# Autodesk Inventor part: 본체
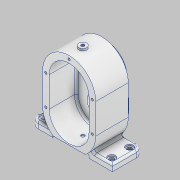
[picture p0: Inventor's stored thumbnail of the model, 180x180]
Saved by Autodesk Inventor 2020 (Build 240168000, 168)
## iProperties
Created: 2021-05
Part Number: 본체
Material: 알루미늄 6061
Document SubType Name: Modeling
Designer: Owner
Density: 2.7 g/cm^3
Appearance: 알루미늄 - 평지
Mass: 669.731 g
Surface Area: 580.57 cm^2
Volume: 248.049 cm^3
Author: Owner
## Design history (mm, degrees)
sketch "스케치3"
  geometry: L1 (0, 0)-(0, 45); L2 (40, 0)-(40, 45); L3 (-40, 45)-(-40, 0); L4 (0, -65)-(0, 110) reference; A1 r 40 centre (0, 0) between (-40, 0) and (40, 0); A2 r 40 centre (0, 45) between (40, 45) and (-40, 45); 1 further point
  constraints: 8 end point, 4 point on circle, 4 tangent, 2 centre point, 2 midpoint, 1 parallel, 1 vertical
  dimensions: "d10" = 40 radius of A2; "d11" = 45 distance of L2.start L2.end
extrude "돌출1" new body sketch "스케치3" distance "d12" = 49; taper "d13" = 0 deg
sketch "스케치4"
  geometry: L1 (0, 45)-(0, 0); L2 (-30, 45)-(-30, 0); L3 (30, 0)-(30, 45); A1 r 30 centre (0, 45) between (30, 45) and (-30, 45); A2 r 30 centre (0, 0) between (-30, 0) and (30, 0); 2 further points
  constraints: 8 end point, 4 point on circle, 4 tangent, 2 centre point, 1 coincident, 1 midpoint, 1 parallel, 1 vertical
  dimensions: "d14" = 45 distance of L3.start L3.end; "d15" = 30 radius of A1
extrude "돌출2" cut sketch "스케치4" distance "d16" = 41; taper "d17" = 0 deg
sketch "스케치5"
  geometry: L1 (0, -65)-(0, 110) reference; C1 r 14 at (0, 45); C2 r 14 at (0, 0); 2 further points
  constraints: 2 centre point, 2 coincident, 1 point on line
  dimensions: "d18" = 45 distance of point (0, 45) point (0, 0); "d19" = 28 diameter of C1; "d20" = 28 diameter of C2
extrude "돌출3" cut sketch "스케치5" distance "d21" = 8; taper "d22" = 0 deg
sketch "스케치6"
  geometry: L1 (0, 45)-(0, 0); L2 (-30, 45)-(-30, 0); L3 (30, 0)-(30, 45); A1 r 30 centre (0, 45) between (30, 45) and (-30, 45); A2 r 30 centre (0, 0) between (-30, 0) and (30, 0); 2 further points
  constraints: 8 end point, 4 point on circle, 4 tangent, 2 centre point, 1 coincident, 1 midpoint, 1 parallel, 1 vertical
  dimensions: "d23" = 30 radius of A1; "d24" = 45 distance of L2.start L2.end
extrude "돌출4" join sketch "스케치6" distance "d25" = 11; taper "d26" = 0 deg
sketch "스케치7"
  geometry: C1 r 14 at (0, 0) reference; C2 r 10 at (0, 0); 1 further point
  constraints: 1 centre point, 1 coincident
  dimensions: "d27" = 20 diameter of C2
extrude "돌출5" cut sketch "스케치7" distance "d28" = 4; taper "d29" = 0 deg
sketch "스케치8"
  geometry: C1 r 11 at (0, 0); 1 further point
  constraints: 1 centre point
  dimensions: "d30" = 22 diameter of C1
extrude "돌출6" cut sketch "스케치8" distance "d31" = 4; taper "d32" = 0 deg
sketch "스케치9"
  geometry: C1 r 14 at (0, 0); 1 further point
  constraints: 1 centre point
  dimensions: "d33" = 28 diameter of C1
extrude "돌출7" cut sketch "스케치9" distance "d34" = 4; taper "d35" = 0 deg
sketch "스케치10"
  geometry: L1 (94.717, -57)-(14.553, -57); L2 (45, -60)-(75, -60) reference; L3 (14.553, -57)-(14.553, -64.954); L4 (14.553, -64.954)-(81.317, -64.954); L5 (81.317, -64.954)-(81.317, -57); 1 further point
  constraints: 8 end point, 2 perpendicular, 1 horizontal, 1 point on line, 1 vertical
  dimensions: "d36" = 3 distance between parallel lines of L2 L1
extrude "돌출8" cut sketch "스케치10" extent not by distance; stored distance "d37" = 0; taper "d38" = 0 deg
sketch "스케치11" dims "d44" = 70
  geometry: L1 (0, -65)-(0, 110) reference; L2 (-56, 0)-(56, 0) reference; C1 r 11 at (0, 45) reference; C2 r 35 at (0, 0); 9 further points
  constraints: 4 point on line, 3 coincident, 2 horizontal alignment, 1 centre point, 2 other
  dimensions: "d39" = 35 distance of C1.centre point (0, 80); "d40" = 35 distance of point (35, 0) point (0, 0); "d41" = 35 distance of point (0, 0) point (-35, 0); "d42" = 35 distance of point (0, -35) point (0, 0); "d43" = 35 distance of C1.centre point (-35, 45); "d45" = 70 diameter of C2
hole "구멍1" sketch "스케치11" at (0, 45), (0, 80), (-35, 45), (35, 45), (35, 0), (-35, 0), (0, -35) diameter "d46" = 3.45873; stored, may be unused: countersink angle "d50" = 90 deg, drill point angle "d52" = 118 deg; dims "d47" = 8, "d48" = 4, "d49" = 2, "d51" = 10
node "작업 평면1"
sketch "스케치12"
  geometry: L1 (-62.167, -3)-(-27.143, -3); L2 (-27.143, -3)-(-27.143, -49); L3 (-27.143, -49)-(-62.167, -49); L4 (-62.167, -49)-(-62.167, -3); L5 (-62.167, -3)-(-27.143, -49); L6 (-27.143, -3)-(-62.167, -49); L7 (27.143, -3)-(59.833, -3); L8 (59.833, -3)-(59.833, -49); L9 (59.833, -49)-(27.143, -49); L10 (27.143, -49)-(27.143, -3); L11 (27.143, -3)-(59.833, -49); L12 (59.833, -3)-(27.143, -49); L13 (40, 0)-(-40, 0) reference; L14 (0, -72)-(0, 12) reference; 3 further points
  constraints: 24 end point, 4 midpoint, 4 parallel, 2 horizontal, 2 perpendicular, 1 other
  dimensions: "d54" = 122 distance between parallel lines of L8 L4; "d55" = 46 distance of L7.end L8.end; "d56" = 46 distance of L3.end L1.start; "d57" = 3 distance between parallel lines of L1 L13; "d58" = 3 distance between parallel lines of L7 L13
extrude "돌출9" join sketch "스케치12" distance "d60" = 10; taper "d61" = 0 deg
sketch "스케치13"
  geometry: L1 (-27.143, -37)-(-27.143, -29.381) reference; L2 (-27.143, -41.755)-(27.316, -41.755); L3 (27.316, -41.755)-(27.316, -32); L4 (27.316, -32)-(-27.143, -32); L5 (-27.143, -32)-(-27.143, -41.755); L6 (27.143, -37)-(59.833, -37) reference; 4 further points
  constraints: 8 end point, 3 perpendicular, 1 horizontal, 1 point on line
  dimensions: "d71" = 5 distance between parallel lines of L4 L6
extrude "돌출10" cut sketch "스케치13" extent not by distance; stored distance "d62" = 0; taper "d63" = 0 deg
sketch "스케치14"
  geometry: L1 (-40, 0)-(40, 0) reference; L2 (62.167, 49)-(29.513, 49) reference; L3 (62.167, 3)-(62.167, 49) reference; L4 (-59.833, 49)-(-59.833, 3) reference; L5 (-29.513, 49)-(-59.833, 49) reference; L6 (-59.833, 3)-(-29.513, 3) reference; C1 r 5.5 at (53.167, 11); C2 r 5.5 at (53.167, 38); C3 r 5.5 at (-50.833, 14); C4 r 5.5 at (-50.833, 38); C5 r 3.3 at (53.167, 11); C6 r 3.3 at (53.167, 38); C7 r 3.3 at (-50.833, 14); C8 r 3.3 at (-50.833, 38); 1 further point
  constraints: 8 centre point, 4 coincident
  dimensions: "d66" = 11 diameter of C1; "d67" = 11 diameter of C2; "d68" = 11 distance from line of C1.centre L1; "d69" = 11 diameter of C3; "d70" = 11 diameter of C4; "d76" = 11 distance from line of C2.centre L2; "d77" = 9 distance from line of L3 C2.centre; "d78" = 9 distance from line of L3 C1.centre; "d79" = 9 distance from line of L4 C3.centre; "d80" = 9 distance from line of L4 C4.centre; "d81" = 11 distance from line of L5 C4.centre; "d82" = 11 distance from line of L6 C3.centre; "d83" = 6.6 diameter of C5; "d84" = 6.6 diameter of C6; "d85" = 6.6 diameter of C7; "d86" = 6.6 diameter of C8
fillet "모깎기3" dims "d72" = 3
sketch "스케치15"
  geometry: L1 (-14.79, -25)-(14.79, -25); L2 (0, -61.4)-(0, 109.4) reference; L3 (-62.167, -37)-(-27.143, -37) reference; 2 further points
  constraints: 2 end point, 2 horizontal, 1 midpoint, 1 point on line
  dimensions: "d73" = 12 distance between parallel lines of L3 L1
extrude "돌출11" join sketch "스케치15" distance "d74" = 0.5; taper "d75" = 0 deg
extrude "돌출12" cut sketch "스케치14" distance "d87" = 2; taper "d88" = 0 deg
extrude "돌출13" cut sketch "스케치14" extent not by distance; stored distance "d89" = 0; taper "d90" = 0 deg
sketch "스케치16"
  geometry: L1 (0, 0)-(0, 65.474); L2 (0, -111.495)-(0, 94.969) reference; 2 further points
  constraints: 2 end point, 2 point on line, 1 vertical
  dimensions: "d91" = 20 distance of L1.start point (0, 20)
hole "구멍2" sketch "스케치16" at (0, 20) diameter "d92" = 3.242; stored, may be unused: countersink angle "d96" = 90 deg, drill point angle "d98" = 118 deg; dims "d93" = 8, "d94" = 4, "d95" = 2, "d97" = 10
sketch "스케치17"
  geometry: L1 (22.978, -23.6)-(22.978, 61.1) reference; 2 further points
  constraints: 1 point on line
  dimensions: "d102" = 21 distance of point (22.978, 28) point (22.978, 49)
hole "구멍3" sketch "스케치17" at (22.978, 28) diameter "d103" = 4.917; stored, may be unused: countersink angle "d107" = 90 deg, drill point angle "d109" = 118 deg; dims "d104" = 12, "d105" = 4, "d106" = 2, "d108" = 17.1
sketch "스케치18" dims "d33" = 28
  geometry: C1 r 2.458 at (22.978, 28) reference; C2 r 6 at (22.978, 28); 2 further points
  constraints: 2 coincident, 1 centre point
  dimensions: "d110" = 12 diameter of C2
extrude "돌출14" cut sketch "스케치18" distance "d111" = 1; taper "d112" = 0 deg
node "작업 평면2"
sketch "스케치19"
  geometry: L1 (0, -72.6)-(0, 12.1) reference; L2 (40, 0)-(-40, 0) reference; C1 r 6 at (0, -20.5); 1 further point
  constraints: 1 centre point, 1 point on line
  dimensions: "d113" = 12 diameter of C1; "d114" = 20.5 distance from line of L2 C1.centre
extrude "돌출15" join sketch "스케치19" distance "d115" = 3; taper "d116" = 0 deg
sketch "스케치20"
  geometry: 2 further points
hole "구멍4" sketch "스케치20" at (0, 0) diameter "d117" = 4.917; stored, may be unused: countersink angle "d121" = 90 deg, drill point angle "d123" = 118 deg; dims "d118" = 12, "d119" = 4, "d120" = 2, "d122" = 17.1
fillet "모깎기4" dims "d124" = 3
fillet "모깎기5" dims "d125" = 3
fillet "모깎기6" dims "d126" = 10
node "솔리드2"
pattern_circular "원형 패턴1" dims angle "d100" = 360 deg
feature "A9D066F2-1C7D-4E18-AEED-F7BC21143FA4" dims "d103" = 4.917, "d104" = 12, "d105" = 4, "d106" = 2, "d107" = 90 deg, "d108" = 17.1, "d109" = 118 deg
other parameters: "d53" = -37
